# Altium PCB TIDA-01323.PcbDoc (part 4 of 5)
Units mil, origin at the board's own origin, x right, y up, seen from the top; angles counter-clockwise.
Board outline 2467 x 6135 mil, 6 copper layers (Layer 1 - Top Layer, Layer 2 - GND, Layer 3 - Sensitive, Layer 4 - GND, Layer 5 - PWR, Layer 6 - Bottom Layer), stack 62.468 mil thick; 310 components, 202 nets, 881 pads, 527 vias.
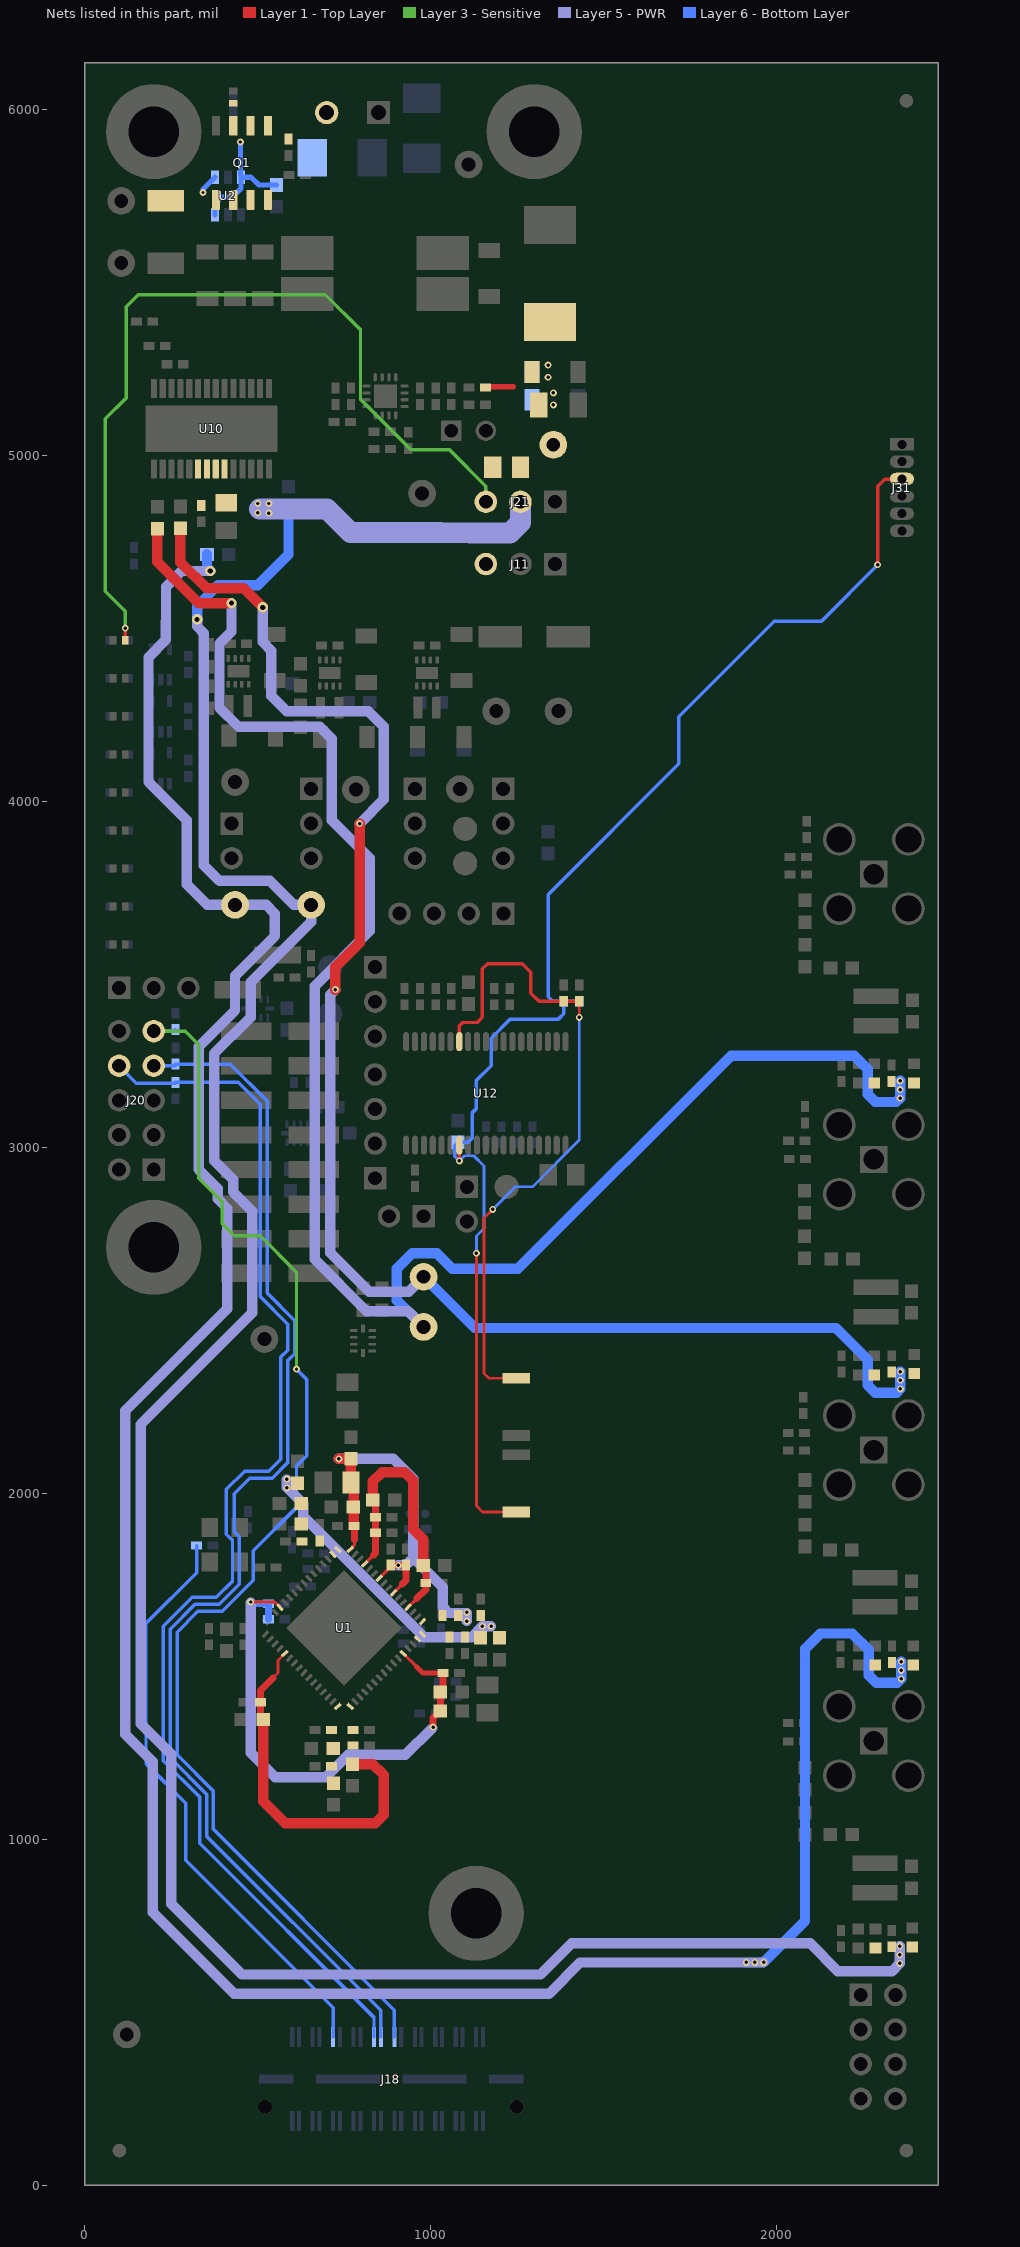
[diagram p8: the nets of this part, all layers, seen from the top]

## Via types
v1: diameter 20, hole 10, Layer 1 - Top Layer to Layer 6 - Bottom Layer, tented both sides, 397 vias
v2: diameter 19.68, hole 7.87, Layer 1 - Top Layer to Layer 6 - Bottom Layer, tented both sides, 64 vias
v3: diameter 12, hole 6, Layer 1 - Top Layer to Layer 6 - Bottom Layer, tented both sides, 58 vias
v4: diameter 30, hole 15, Layer 1 - Top Layer to Layer 6 - Bottom Layer, tented both sides, 8 vias

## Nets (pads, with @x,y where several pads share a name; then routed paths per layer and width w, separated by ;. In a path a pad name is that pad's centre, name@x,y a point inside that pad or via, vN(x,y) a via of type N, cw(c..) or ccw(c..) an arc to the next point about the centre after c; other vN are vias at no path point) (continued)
SPI_MOSI_0: J18.18 J20.8 R56.2 | length 3681.3
  Layer 6 - Bottom Layer w10: J20.8@99.38,3235.87 149.38,3185.87 R56.2@262,3185.87 ; R56.2@262,3187.62 443.38,3187.62 507,3124 507,2569 587,2489 587,2414 567,2394 567,2099 532,2064 462,2064 409.38,2011.38 409.38,1881.62 427,1864 427,1745.57 380.43,1699 310.43,1699 227,1615.57 227,1227.28 332,1122.28 332,989 836.01,484.99 J18.18@836.01,428.52
SPI_NCS_0: J18.22 J20.9 R58.2 | length 3708.8
  Layer 3 - Sensitive w10: J20.9@199.38,3335.87 290.13,3335.87 329.38,3296.62 329.38,2910.75 397,2843.13 397,2779 432,2744 507,2744 612,2639 v1(612,2359)
  Layer 6 - Bottom Layer w10: J20.9@199.38,3335.87 257.49,3335.87 R58.2@262,3340.38 ; v1(612,2359) 642,2329 642,2109 612,2079 612,1959 487,1834 487,1749 397,1659 327,1659 267,1599 267,1243.85 372,1138.85 372,1029 895.06,505.94 J18.22@895.06,428.52
SPI_SCLK_0: J18.20 J20.7 R57.2 | length 3603.1
  Layer 6 - Bottom Layer w10: J20.7@199.38,3235.87 R57.2@262,3235.87 ; R57.2@262,3240.38 420.62,3240.38 527,3134 527,2579 607,2499 607,2404 587,2384 587,2089 542,2044 477,2044 432,1999 432,1889 447,1874 447,1737.28 388.72,1679 318.72,1679 247,1607.28 247,1235.57 352,1130.57 352,1009 855.69,505.31 J18.20@855.69,428.52
SYS_CLK_25MHZ: J18.10 R45.2 | length 1705.2
  Layer 6 - Bottom Layer w10: R45.2@323.38,1849 323.38,1770.38 177,1624 177,1219 292,1104 292,939 717.9,513.1 J18.10@717.9,428.52
TDIO1: C107.1 J31.3 R92.1 R103.1 S1.1 U12.7 | length 4074.7
  Layer 1 - Top Layer w8: v1(1132,2694) 1132,1964.09 1150,1946.09 S1.1@1247.38,1946.09
  Layer 1 - Top Layer w10: v1(1082.61,2960.87) U12.7@1082.61,3006.26 ; v1@2292.38,4683.49 2292.38,4910.87 2312.38,4930.87 J31.3@2367.38,4930.87
  Layer 6 - Bottom Layer w8: v1(1082.61,2960.87) 1097.61,2975.87 1124.38,2975.87 1154.38,2945.87 1154.38,2765.87 1132,2743.49 v1(1132,2694)
  Layer 6 - Bottom Layer w10: v1(1082.61,2960.87) 1069.38,2974.1 1069.38,3004.37 R103.1@1079.38,3014.37 1107.88,3014.37 1119.38,3025.87 1119.38,3099.3 1130.95,3110.87 1130.95,3192.44 1174.38,3235.87 1174.38,3315.87 1229.38,3370.87 1369.38,3370.87 1384.38,3385.87 R92.1@1384.38,3422.25 ; C107.1@1429.38,3422.25 R92.1@1384.38,3422.25 ; v1(2292,4684) 2292,4683.49 2129.51,4521 1993,4521 1717,4245 1717,4108.49 1339.38,3730.87 1339.38,3435.87 1353,3422.25 R92.1@1384.38,3422.25
USER_BUTTON: C111.1 R110.1 S2.1 U12.32 | length 1946.5
  Layer 1 - Top Layer w8: v1(1179.38,2820.87) 1154.38,2795.87 1154.38,2346.62 1168.32,2332.68 S2.1@1247.38,2332.68 ; v1(1429.38,3375.87) C111.1@1429.38,3422.25
  Layer 1 - Top Layer w10: U12.32@1082.61,3305.48 1082.61,3350.87 1092.61,3360.87 1134.38,3360.87 1149.38,3375.87 1149.38,3515.87 1164.38,3530.87 1264.38,3530.87 1289.38,3505.87 1289.38,3445.87 1313,3422.25 R110.1@1384.38,3422.25 C111.1@1429.38,3422.25
  Layer 6 - Bottom Layer w8: v1(1179.38,2820.87) 1244.38,2885.87 1294.38,2885.87 1429.38,3020.87 v1(1429.38,3375.87)
V_CAM: C96.1 C97.1 J21.2 U10.20 U10.21 U10.22 U10.23 | length 855
  Layer 5 - PWR w60: 505,4845 700,4845 768,4777 1028,4777 1114.38,4775.87 1229.38,4775.87 1259.38,4805.87 J21.2@1259.38,4865.87
  other v1: 532,4833 500,4834 500,4861 532,4861
V_CAM1: C3.1 C4.1 L1.1 R64.1 TP21.1 | length 7111.6
  Layer 5 - PWR w30: v4(324.73,4526) 324.73,4505.51 344.38,4485.87 344.38,3815.87 389.38,3770.87 534.38,3770.87 604.38,3700.87 TP21.1@654.38,3700.87 654.38,3651.87 479.38,3476.87 479.38,3376.38 374.38,3271.38 374.38,2960.87 429.38,2905.87 429.38,2870.87 484.38,2815.87 484.38,2521.38 162,2199 162,1334 250.28,1245.72 250.28,814 455.28,609 1317,609 1407,699 2097,699 2177,619 2333.49,619 v1(2355.62,641.13) v1(2355.62,691.13)
  Layer 6 - Bottom Layer w30: v4(324.73,4526) 324.73,4564.73 385,4625 500,4625 589,4714 R64.1@589,4846.5
  other v1: 2355.62,666.13
V_CAM2: C7.1 C8.1 L2.1 R66.1 TP22.1 | length 7949.6
  Layer 5 - PWR w30: v4(363,4666) 281,4666 234.95,4619.95 234.95,4582 234.38,4466.74 184.38,4416.74 184.38,4055.87 294.38,3945.87 294.38,3760.87 354.38,3700.87 TP22.1@434.38,3700.87 524.38,3700.87 549.38,3675.87 549.38,3610.87 434.38,3495.87 434.38,3396.38 329.38,3291.38 329.38,2935.87 384.38,2880.87 384.38,2850.87 412,2823.25 412,2534 117,2239 117,1304 197,1224 197,789 432,554 1342,554 1432,644 v1(1912,644) v1(1937,644) v1(1962,644)
  Layer 6 - Bottom Layer w10: v4(363,4666) v4@363,4674.73
  Layer 6 - Bottom Layer w30: R66.1@353.5,4714 353.5,4675.5 v4(363,4666) ; v1(1912,644) v1(1962,644) 2082,764 2082,1551 2125.72,1594.72 2218.72,1594.72 2265.94,1547.5 2265.94,1474.42 2287.87,1452.49 2349.13,1452.49 v1(2360,1463.36) v1(2360,1513.36)
  other v1: 2360,1488.36
V_CAM3: C17.1 C18.1 L9.1 R78.1 TP23.1 | length 4550.8
  Layer 1 - Top Layer w30: R78.1@276.29,4789.5 276.29,4691.71 352,4616 459.26,4616 v4(514.38,4560.87) ; v1(724.38,3455.87) 724.38,3520.87 794.38,3590.87 v1(794.38,3935.87)
  Layer 5 - PWR w30: v4(514.38,4560.87) 514.38,4460.87 539.38,4435.87 539.38,4305.87 584.38,4260.87 819.38,4260.87 864.38,4215.87 864.38,4005.87 v1(794.38,3935.87) ; v1(724.38,3455.87) 709.38,3440.87 709.38,2695.87 822.73,2582.52 936.03,2582.52 TP23.1@979.38,2625.87
  Layer 6 - Bottom Layer w30: TP23.1@979.38,2625.87 1127.25,2478 2171.33,2478 2263.32,2386.01 2263.32,2312.93 2285.25,2291 2346.51,2291 v1(2357.38,2301.87) v1(2357.38,2326.87) v1(2357.38,2351.87)
V_CAM4: C21.1 C22.1 L10.1 R80.1 TP24.1 | length 5150.6
  Layer 1 - Top Layer w30: R80.1@209.81,4787.5 209.81,4692.19 329,4573 v4(424,4573)
  Layer 5 - PWR w30: v4(424,4573) 424,4490.49 389.38,4455.87 389.38,4270.87 444.38,4215.87 679.38,4215.87 714.38,4180.87 714.38,3945.87 824.38,3835.87 824.38,3625.87 664.38,3465.87 664.38,2675.87 814.38,2525.87 934.38,2525.87 TP24.1@979.38,2480.87
  Layer 6 - Bottom Layer w30: TP24.1@979.38,2480.87 902,2558.25 902,2649 947,2694 1017,2694 1062,2649 1252,2649 1868,3265 2224.08,3265 2262.94,3226.14 2262.94,3153.06 2284.87,3131.13 2346.13,3131.13 v1(2357,3142) v1(2357,3192)
  other v1: 2357,3167
V_MAIN: D5.2 J11.3 J21.3 R19.2 | length 2459.8
  Layer 1 - Top Layer w10: D5.2@117.1,4465.87 v1(117.1,4500.87)
  Layer 3 - Sensitive w10: v1(117.1,4500.87) 117.1,4549.9 59.38,4607.62 59.38,5105.87 119.38,5165.87 119.38,5430 154.38,5465 695.25,5465 797,5363.25 797,5162 943.13,5015.87 1054.38,5015.87 1159.38,4910.87 J21.3@1159.38,4865.87
VBAT: C29.1 C30.1 D1.1 D2.1 J5.2 Q1.1 Q1.2 Q1.3 U2.3 U2.6 | length 364.4
  Layer 6 - Bottom Layer w15: U2.3@376.52,5695.87 376.52,5727.52 395,5746 426,5746 451.33,5771.33 U2.6@451.33,5804.13 480.87,5804.13 503.5,5781.5 C30.1@553.67,5781.5 ; U2.6@450,5810.7 v1(450,5906)
VBAT_PROTECT: Q1.5 Q1.6 Q1.7 Q1.8 R17.1 U2.4 | length 58.5
  Layer 6 - Bottom Layer w15: v1(341.78,5760) 341.78,5769.39 U2.4@376.52,5804.13
VDD18_P0: C67.1 C68.1 C69.1 C71.1 C72.1 C75.1 C76.1 C78.1 C79.1 L23.2 U1.1 U1.2 U1.47 U1.48 | length 824.9
  Layer 5 - PWR w30: v1@584.38,2039 584.38,2017.87 632,1970.25 632,1934 981.51,1584.49 1118,1584.49 v1(1149.38,1615.87) v1(1174.38,1615.87)
  other v1: 584.38,2015.87 584.38,2040.87
VDD18A: C57.1 C58.1 C59.1 L21.2 U1.32
VDDCSI_1V1: C88.1 C89.1 C90.1 C91.1 L25.2 U1.21 U1.33 | length 1063.3
  Layer 1 - Top Layer w8: 543.88,1466.37 558.22,1480.71 558.22,1517.17 U1.21@578.16,1537.11
  Layer 1 - Top Layer w20: C89.1@515.88,1345.87 508,1353.74 C90.1@508,1395.87 508,1430.49 543.88,1466.37
  Layer 1 - Top Layer w30: C89.1@515.88,1345.87 515.88,1109.37 579.38,1045.87 839.38,1045.87 864.38,1070.87 864.38,1185.87 832.88,1217.37 L25.2@774.38,1217.37
VDDFPD18: C60.1 C61.1 C62.1 C63.1 C64.1 C65.1 C66.1 L22.2 U1.49 U1.55 U1.58 U1.64 | length 1282.6
  Layer 1 - Top Layer w9: U1.64@767.45,1837.78 779.38,1849.71 779.38,1865.87 ; U1.58@850.99,1754.24 C64.1@884.38,1787.64 ; U1.55@892.75,1712.48 917.76,1737.49
  Layer 1 - Top Layer w20: C65.1@778,1905.87 779.38,1904.49 779.38,1865.87 ; C64.1@884.38,1792.25 884.76,1791.87 v1(906.38,1791.87) C61.1@928,1791.87 ; 917.76,1737.49 928.38,1748.1 C61.1@928.38,1792.25
  Layer 1 - Top Layer w30: v1(734.38,2099.37) L22.2@769.38,2099.37 ; L22.2@769.38,2094.37 769.38,2025.87 778,2017.25 C65.1@778,1905.87
  Layer 5 - PWR w30: v1(734.38,2099.37) 891.63,2099.37 949.38,2041.62 949.38,1813.25 ; v1(906.38,1791.87) 928,1791.87 949.38,1813.25 ; v1(1104.38,1630.87) 1104.38,1654 1052,1654 1034.38,1671.62 1034.38,1728.25 949.38,1813.25
  other v1: 1104.38,1655.87
VDDFPD_1V1: C92.1 C93.1 C94.1 C95.1 L26.2 U1.52 U1.61 | length 794
  Layer 1 - Top Layer w9: U1.61@809.22,1796.01 834.23,1821.02 ; U1.52@934.52,1670.71 959.53,1695.72
  Layer 1 - Top Layer w20: L26.2@832.88,1980.87 840.76,1973 C92.1@840.76,1930.87 C95.1@840.76,1885.87 840.76,1827.55 834.23,1821.02 ; 959.53,1695.72 985.76,1721.94 C94.1@985.76,1740.87 985.76,1783 C93.1@977.88,1790.87
  Layer 1 - Top Layer w30: L26.2@832.88,1980.87 832.88,2034.37 859.38,2060.87 924.38,2060.87 949.38,2035.87 949.38,1895.87 977.88,1867.37 C93.1@977.88,1790.87
VDDL_1V1: C81.1 C82.1 C83.1 C84.1 L24.2 U1.13 U1.44 | length 1539.1
  Layer 1 - Top Layer w8: v1(479.38,1685.87) 549.1,1685.87 U1.13@564.25,1670.72
  Layer 1 - Top Layer w9: U1.44@920.59,1537.1 959.38,1498.31
  Layer 1 - Top Layer w15: 959.38,1498.31 976.82,1480.87 C84.1@1035.76,1480.87
  Layer 1 - Top Layer w20: v1(1007,1324) 1007,1349.99 L24.2@1027.88,1370.87 C82.1@1027.88,1425.87 ; C82.1@1027.88,1430.87 1035.76,1438.74 C84.1@1035.76,1480.87
  Layer 5 - PWR w30: v1@479.38,1684 479.38,1250.5 550.88,1179 697,1179 762,1244 927,1244 v1@1004.5,1321.5
  Layer 6 - Bottom Layer w20: v1(479.38,1685.87) 484.38,1680.87 C83.1@530.76,1680.87 C81.1@530.76,1635.87
VOUT_SEPIC: C33.1 C34.1 C35.1 D4.1 R19.1 R20.2 R24.1 TP6.1 | length 79.4
  Layer 1 - Top Layer w15: R24.1@1160.01,5198.37 1239.38,5198.37
  other v1: 1354.38,5145.87 1354.38,5180.87 1339.38,5225.87 1339.38,5260.87
pads on no net: FID1.1 FID2.1 FID3.1 FID4.1 FID5.1 FID6.1 H1. H2. H3. H4. J18.MH1 J18.MH2 J20.4 J20.6 J31.1 J31.6 R52.2 U1.7 U1.8 U10.2 U10.19 U10.24 U10.29@366,5077 U12.23 U14.1 U14.2 U15.1 U15.2

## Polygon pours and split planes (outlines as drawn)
GND on Layer 2 - GND "Layer 2 - GND - GND" (solid, remove dead copper, pour order 0): 20,6115 20,20 2447,20 2447,6115
GND on Layer 4 - GND "Layer 4 - GND - GND" (solid, remove dead copper, pour order 2): 20,6115 20,20 2447,20 2447,6115

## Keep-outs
Keep-Out Layer:
  text ".Layer_Name" at -2051,-674.49 h60

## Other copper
Layer 1 - Top Layer:
  region net NetR64_2: 498,4988.39 541,4988.39 541,4895 498,4895
  region net NetR66_2: 447,4932 447,4988 490.47,4988 490.47,4895 447,4895
  region net GND: 311,4743 311,4826 371.6,4826 383.6,4814 441,4814 453,4802 489,4802 489,4798 489,4743
  region net VDD18_P0: 698.38,1878.87 660.38,1878.87 646.38,1892.87 646.38,2038.87 634.38,2050.87 579.38,2050.87 574.38,2045.87 574.38,2010.87 579.38,2005.87 596.38,2005.87 605.38,1996.87 605.38,1979.87 605.38,1888.87 611.38,1882.87 611.38,1848.87 614.38,1845.87 688.38,1845.87 722.38,1811.87 743.38,1832.87 744.38,1832.87
  region net GND: 597.38,1848.87 597.38,1872.87 583.38,1886.87 583.38,1989.87 542.38,1989.87 519.38,1966.87 519.38,1893.87 564.38,1848.87
  region net GND: 474.38,1580.87 474.38,1545.87 452.38,1523.87 386.38,1523.87 374.38,1535.87 324.38,1535.87 319.38,1540.87 319.38,1575.87 324.38,1580.87 374.38,1580.87 389.38,1565.87 429.38,1565.87 444.38,1580.87
  region net GND: 684.38,1327.87 684.38,1198.87 649.38,1198.87 634.38,1213.87 634.38,1312.87 649.38,1327.87
  region net VDD18A: 696.38,1355.87 696.38,1141.87 738.38,1141.87 742.38,1145.87 742.38,1389.87 736.38,1395.87
  region net VDD18_P0: 966.38,1567.87 1119.38,1567.87 1125.38,1561.87 1224.38,1561.87 1224.38,1630.87 1189.38,1665.87 1131.38,1665.87 1131.38,1612.87 1122.38,1603.87 1102.38,1603.87 970.38,1603.87 950.38,1583.87
  region net GND: 479.38,1410.87 419.38,1410.87 409.38,1400.87 409.38,1330.87 419.38,1320.87 479.38,1320.87
  region net GND: 794.38,2285.87 794.38,2345.87 724.38,2345.87 704.38,2325.87 704.38,2285.87
  region net GND: 747.38,1892.87 668.38,1892.87 664.38,1896.87 664.38,2062.87 715.38,2062.87 715.38,1997.87 739.38,1973.87 739.38,1925.87 747.38,1917.87
  region net GND: 839.38,1327.87 839.38,1258.87 805.38,1258.87 805.38,1327.87
  region net GND: 1014.38,1685.87 1022.38,1677.87 1109.38,1677.87 1114.38,1682.87 1114.38,1720.87 1109.38,1725.87 1079.38,1725.87 1064.38,1740.87 1064.38,1825.87 1059.38,1830.87 1019.38,1830.87 1014.38,1825.87
  region net GND: 1042.38,1553.87 1111.38,1553.87 1125.38,1539.87 1218.38,1539.87 1218.38,1440.87 1197.38,1419.87 1124.38,1419.87 1111.38,1406.87 1071.38,1406.87 1066.38,1411.87 1066.38,1496.87 1042.38,1520.87
  region net VDDFPD18: 970.38,1617.87 1109.38,1617.87 1114.38,1622.87 1114.38,1660.87 1109.38,1665.87 1005.38,1665.87 964.38,1624.87 964.38,1623.87
  region net VDDCSI_1V1: 762.38,1395.87 794.38,1363.87 794.38,1195.87 754.38,1195.87 754.38,1387.87
  region net GND: 409.38,4361.87 413.38,4357.87 482.38,4357.87 488.38,4363.87 510.38,4363.87 516.38,4357.87 516.38,4134.87 581.38,4134.87 581.38,4358.87 595.38,4372.87 642.38,4372.87 662.38,4352.87 742.38,4352.87 747.38,4357.87 773.38,4357.87 778.38,4352.87 778.38,4230.87 767.38,4219.87 767.38,4151.87 839.38,4151.87 850.38,4162.88 863.38,4175.87 863.38,4361.87 874.38,4372.87 937.38,4372.87 957.38,4352.87 1024.38,4352.87 1030.38,4358.87 1050.38,4358.87 1056.38,4352.87 1056.38,4230.87 1043.38,4217.87 1043.38,4139.87 1112.38,4139.87 1121.38,4148.87 1121.38,4230.87 1121.38,4399.87 1102.38,4418.87 1013.38,4418.87 1013.38,4393.87 1008.38,4388.87 973.38,4388.87 965.38,4396.87 965.38,4416.87 961.38,4420.87 736.38,4420.87 732.38,4416.87 732.38,4392.87 728.38,4388.87 690.38,4388.87 684.38,4394.87 684.38,4416.87 677.38,4423.87 470.38,4423.87 468.38,4421.87 468.38,4397.87 464.38,4393.87 427.38,4393.87 420.38,4400.87 420.38,4421.87 415.38,4426.87 409.38,4426.87
  region net V_CAM3: 2265.38,2368.87 2414.38,2368.87 2414.38,2305.87 2397.51,2289 2287.25,2289 2265.38,2310.87
  region net NetC29_2: 569.38,5885.87 569.38,5795.87 609.38,5795.87 609.38,5885.87
  region net GND: 2172.38,2368.87 2254.38,2368.87 2254.38,2325.87 2246.51,2318 2183.25,2318 2172.38,2328.87
  region net GND: 2170.62,706 2255.62,706 2255.62,673.13 2235.62,653.13 2185.62,653.13 2170.62,668.13
  region net NetC15_1: 2221.72,2544 2413,2544 2413,2448 2318,2448 2300,2430 2300,2381 2174,2381 2174,2430 2221.72,2490
  region net NetL3_1: 2101.62,1164.13 2101.62,1128.63 2101.62,1087.63 2101.62,1055.63 2058.84,1055.63 2058.84,1070.63 2058.84,1090.63 2058.84,1117.27 2058.84,1141.63 2058.84,1164.13
  region net NetC1_1: 2218.62,878.13 2410.62,878.13 2410.62,788.13 2315.62,788.13 2302.62,775.13 2302.62,721 2168.62,721 2168.62,768.13 2218.62,818.13
  region net NetL4_1: 2410.62,900.13 2410.62,1053.13 2390.62,1053.13 2325.62,1053.13 2259.62,1053.13 2209.62,1053.13 2194.62,1038.13 2194.62,985.13 2218.62,953.13 2218.62,900.13
  region net GND: 1459.38,5295.87 1409.38,5295.87 1400.38,5286.87 1400.38,5089.87 1409.38,5080.87 1459.38,5080.87
  region net LOCAL_1V1: 440.38,4348.87 440.38,4235.87 474.38,4201.87 474.38,3900.87 389.38,3900.87 374.38,3915.87 374.38,4205.87 334.38,4245.87 334.38,4290.87 379.38,4290.87 399.38,4310.87 417.38,4310.87 429.38,4322.87 429.38,4348.87
  region net VBAT_PROTECT: 544.38,5770.87 179.38,5770.87 179.38,5680.87 199.38,5660.87 524.38,5660.87 544.38,5680.87
  region net VBAT: 709.38,6030.87 739.38,6000.87 739.38,5925.87 709.38,5895.87 414.38,5895.87 414.38,6030.87
  region net GND: 874.38,5241.36 884.38,5251.36 1026.38,5251.36 1026.38,5178.36 955.38,5178.36 933.38,5156.36 908.38,5156.36 903.38,5151.36 903.38,5137.36 872.38,5137.36 864.38,5129.36 864.38,5099.36 852.38,5087.36 852.38,4991.36 738.89,4991.36 674.38,5055.87 674.38,5164.36 736.38,5164.36 736.38,5078.36 748.38,5066.36 803.38,5066.36 835.38,5098.36 835.38,5205.36 869.38,5205.36 874.38,5210.36
  region net GND: 1334.38,4565.87 1334.38,4385.87 1464.38,4385.87 1464.38,4565.87
  region net NetL20_1: 448.38,4348.87 448.38,4250.87 458.38,4240.87 484.38,4240.87 484.38,4307.87 477.38,4314.87 466.38,4314.87 459.38,4321.87 459.38,4348.87
  region net NetL19_1: 712.38,4343.87 712.38,4245.87 722.38,4235.87 748.38,4235.87 748.38,4302.87 741.38,4309.87 730.38,4309.87 723.38,4316.87 723.38,4343.87
  region net LOCAL_1V8: 693.38,4343.87 693.38,4317.87 685.38,4309.87 667.38,4309.87 659.38,4301.87 659.38,4247.87 647.38,4235.87 603.38,4235.87 603.38,3990.87 799.38,3990.87 823.38,4014.87 823.38,4056.87 799.38,4080.87 734.38,4080.87 704.38,4110.87 704.38,4343.87
  region net NetC36_1: 54.38,5605.87 84.38,5635.87 769.38,5635.87 834.38,5570.87 834.38,5370.87 784.38,5320.87 784.38,5197.87 796.38,5185.87 826.38,5185.87 826.38,5175.87 709.38,5175.87 699.38,5185.87 699.38,5370.87 739.38,5410.87 739.38,5518.87 723.38,5534.87 343.38,5534.87 319.38,5510.87 84.38,5510.87 54.38,5540.87
  region net NetC32_2: 805.38,5194.87 800.38,5199.87 800.38,5306.87 854.38,5360.87 854.38,5430.87 939.38,5515.87 1179.38,5515.87 1204.38,5490.87 1204.38,5375.87 1114.38,5285.87 895.38,5285.87 864.38,5254.87 864.38,5216.87 861.38,5213.87 832.38,5213.87 826.38,5207.87 826.38,5197.87 823.38,5194.87
  region net NetC32_1: 958.38,5534.87 1363.38,5534.87 1424.38,5595.87 1424.38,5725.87 1043.38,5725.87 958.38,5640.87
  region net VOUT_SEPIC: 1424.38,5445.87 1269.38,5445.87 1254.38,5430.87 1254.38,5220.87 1239.38,5205.87 1239.38,5190.87 1254.38,5175.87 1254.38,5030.87 1234.38,5010.87 1234.38,4933.87 1242.38,4925.87 1384.38,4925.87 1394.38,4935.87 1399.63,4941.12 1399.63,5065.62 1384.38,5080.87 1384.38,5294.87 1394.38,5304.87 1424.38,5334.87
  region net GND: 716.38,5519.87 721.38,5514.87 721.38,5417.87 694.38,5390.87 564.38,5390.87 526.88,5428.37 319.38,5428.37 319.38,5485.87 353.38,5519.87
  region net V_CAM: 317.62,4837 317.62,4988.87 414,4988.87 414,4916 437.95,4892.05 454,4876 551,4876 551,4819.99 551,4818.68 453.32,4818.68 435,4837
  region net EXT_VIN: 1324.38,4900.87 1394.38,4900.87 1394.38,4650.87 1324.38,4650.87
  region net V_MAIN: 1124.38,5005.87 1204.38,5005.87 1204.38,4650.87 1124.38,4650.87
  region net NetL18_1: 993.38,4343.87 993.38,4245.87 1003.38,4235.87 1029.38,4235.87 1029.38,4302.87 1022.38,4309.87 1011.38,4309.87 1004.38,4316.87 1004.38,4343.87
  region net NetC43_1: 1294.38,4720.87 1294.38,4295.87 1214.38,4215.87 1144.38,4215.87 1144.38,4405.87 1112.38,4437.87 1016.38,4437.87 1004.38,4425.87 1004.38,4397.87 993.38,4397.87 993.38,4471.87 979.38,4485.87 897.88,4485.87 848.38,4436.37 735.88,4436.37 723.38,4423.87 723.38,4397.87 711.88,4397.87 711.88,4479.37 705.38,4485.87 674.38,4485.87 654.38,4485.87 610.38,4441.87 472.38,4441.87 459.38,4428.87 459.38,4402.87 448.38,4402.87 448.38,4494.87 474.38,4520.87 514.38,4520.87 674.38,4520.87 699.38,4545.87 1009.38,4545.87 1144.38,4545.87 1224.38,4625.87 1224.38,4720.87
  region net LOCAL_3V3: 974.38,4343.87 974.38,4317.87 966.38,4309.87 948.38,4309.87 894.25,4309.87 884.38,4300 884.38,4002.87 1049.38,4002.87 1057.38,3994.87 1103.38,3994.87 1111.38,4002.87 1124.38,4015.87 1124.38,4055.87 1099.38,4080.87 1015.38,4080.87 985.38,4110.87 985.38,4343.87
  region net V_CAM1: 2268.62,706 2412.62,706 2412.62,645.13 2398.62,631.13 2287.62,631.13 2268.62,650.13
  region net GND: 20,6115 20,40 40,40 40,6095 2426,6095 2426,40 20,40 20,20 2447,20 2447,6115
  region net GND: 2320,5001 2320,4963 2403,4963 2403,5001
  region net NetL3_2: 2175.62,980.13 2175.62,1034.13 2054.62,1034.13 2054.62,980.13
  region net NetL5_1: 2062.61,1888.87 2062.61,1923.87 2062.61,1961.87 2062.61,1995.87 2105.95,1995.87 2105.95,1980.87 2105.95,1957.87 2105.95,1926.3 2105.95,1902.87 2105.95,1888.87
  region net NetL5_2: 2174.62,1816.13 2174.62,1869.13 2051.49,1869.13 2051.49,1829.13 2051.49,1816.13
  region net NetL12_1: 2412.5,2563 2412.5,2715 2392.5,2715 2327.5,2715 2261.5,2715 2211.5,2715 2197.5,2701 2197.5,2645.24 2221.5,2616.98 2221.5,2563
  region net NetL11_1: 2100.67,2831 2100.67,2801.77 2100.67,2760 2100.67,2724 2057.33,2724 2057.33,2736 2057.33,2763 2057.33,2793.57 2057.33,2819 2057.33,2831
  region net NetL13_1: 2060.74,3561.02 2060.74,3597.94 2060.74,3641 2060.74,3669.02 2103.8,3669.02 2103.8,3664.02 2103.8,3654.02 2103.8,3631.94 2103.8,3597.94 2103.8,3561.02
  region net NetL13_2: 2185.07,3494 2185.07,3544 2061.94,3544 2061.94,3524 2061.94,3503 2061.94,3494
  region net NetL11_2: 2179.5,2649 2179.5,2703 2058.5,2703 2058.5,2649
  region net GND: 2122,1234 2122,1135 2437,1135 2437,1435 2122,1435 2122,1334 2347,1334 2347,1234
  region net NetL6_1: 2409.62,1722.13 2409.62,1875.13 2389.62,1875.13 2324.62,1875.13 2258.62,1875.13 2208.62,1875.13 2193.62,1860.13 2193.62,1807.13 2217.62,1775.13 2217.62,1722.13
  region net NetC5_1: 2218.62,1702.13 2410.62,1702.13 2410.62,1612.13 2315.62,1612.13 2302.62,1599.13 2302.62,1542.13 2168.62,1542.13 2168.62,1592.13 2218.62,1642.13
  region net GND: 2169,1528 2254,1528 2254,1486 2243,1475 2181,1475 2169,1487
  region net V_CAM2: 2268,1528 2412,1528 2412,1463 2398,1449 2287,1449 2268,1468
  region net GND: 2320,721 2431,721 2431,769 2335,769 2320,754
  region net GND: 2319,1542 2430,1542 2430,1588 2334,1588 2319,1573
  region net GND: 2318.38,2380.87 2429.38,2380.87 2429.38,2426.87 2333.38,2426.87 2318.38,2411.87
  region net GND: 2172,3209 2254,3209 2254,3166 2245.87,3157.87 2183.13,3157.87 2172,3169
  region net V_CAM4: 2265,3209 2414,3209 2414,3146 2397.13,3129.13 2286.87,3129.13 2265,3151
  region net GND: 2318,3221 2429,3221 2429,3267 2333,3267 2318,3252
  region net NetC19_1: 2221.34,3384.13 2412.62,3384.13 2412.62,3288.13 2317.62,3288.13 2299.62,3270.13 2299.62,3221.13 2173.62,3221.13 2173.62,3270.13 2221.34,3330.13
  region net NetL14_1: 2412.5,3404 2412.5,3556 2392.5,3556 2327.5,3556 2261.5,3556 2211.5,3556 2197.5,3542 2197.5,3486.24 2221.5,3457.98 2221.5,3404
  region net GND: 2121.3,2074 2121.3,1975 2436.3,1975 2436.3,2275 2121.3,2275 2121.3,2174 2346.3,2174 2346.3,2074
  region net GND: 2121.3,2914 2121.3,2815 2436.3,2815 2436.3,3115 2121.3,3115 2121.3,3014 2346.3,3014 2346.3,2914
  region net GND: 2123.3,3741 2123.3,3640 2438.3,3640 2438.3,3940 2123.3,3940 2123.3,3841 2348.3,3841 2348.3,3741
  region net GND: 1207,2184 1207,2094 1287,2094 1287,2184
  region net GND: 174.62,5009.06 174.62,5144.93 216,5144.93 216,5328 261,5328 261,5145 523,5145 523,5220 557,5220 557,5144.93 557,5009.07 234,5009.06
  region net NetR80_2: 190,4932 190,4988 233.47,4988 233.47,4895 190,4895
  region net NetR78_2: 242,4988.39 285,4988.39 285,4895 242,4895
  text ".Layer_Name" at -2051,-674.49 h60
Layer 2 - GND:
  pour cut-out: 774.39,1830.88 969.39,1635.88 1004.39,1635.88 1004.39,1665.88 804.39,1865.88 774.39,1865.88
  region net GND: 1469.38,4150.87 1459.38,4150.87 1459.38,3820.87 1469.38,3820.87
  pour cut-out: 2311.5,4963 2311.5,4743 2411.5,4743 2411.5,4963
  region net GND: 992.87,2895.39 992.87,2886.36 979.38,2872.87 971.38,2872.87 971.38,2895.39
  region net GND: 1276.38,2945.87 1290.38,2959.87 1294.38,2959.87 1294.38,2925.87 1288.38,2925.87 1276.38,2937.87
  pour cut-out: 789.38,3560.87 789.38,3360.87 889.38,3360.87 889.38,3560.87
  pour cut-out: 889.38,3160.87 889.38,2860.87 789.38,2860.87 789.38,3160.87
  pour cut-out: 1029.38,2750.87 1029.38,2850.87 829.38,2850.87 829.38,2750.87
  pour cut-out: 1054.38,2735.87 1154.38,2735.87 1154.38,2921.37 1134.88,2940.87 1054.38,2940.87
  pour cut-out: 1014.38,5120.87 1014.38,5025.87 1204.38,5025.87 1204.38,5120.87
  pour cut-out: 1109.38,4815.87 1409.38,4815.87 1409.38,4915.87 1109.38,4915.87
  pour cut-out: 1109.38,4735.87 1109.38,4635.87 1409.38,4635.87 1409.38,4735.87
  pour cut-out: 959.38,3725.87 959.38,3625.87 1259.38,3625.87 1259.38,3725.87
  pour cut-out: 1159.38,4085.87 1159.38,3785.87 1259.38,3785.87 1259.38,4085.87
  pour cut-out: 904.38,4085.87 904.38,3785.87 974.38,3785.87 1004.38,3815.87 1004.38,4085.87
  pour cut-out: 604.38,4085.87 604.38,3785.87 704.38,3785.87 704.38,4085.87
  pour cut-out: 374.38,3985.87 374.38,3785.87 474.38,3785.87 474.38,3985.87
  pour cut-out: 49.38,3510.87 49.38,3410.87 349.38,3410.87 349.38,3510.87
  pour cut-out: 149.38,3385.87 149.38,3285.87 49.38,3285.87 49.38,2985.87 149.38,2985.87 149.38,2885.87 249.38,2885.87 249.38,3385.87
  region net GND: 1459.38,700.87 1459.38,300.87 1479.38,300.87 1479.38,700.87
  pour cut-out: 2195,599.87 2195,199.87 2390,199.87 2390,599.87
  pour cut-out: 773.71,1390.2 913.71,1530.2 948.71,1530.2 948.71,1500.2 808.71,1360.2 773.71,1360.2
  pour cut-out: 584.38,1530.87 724.38,1390.87 724.38,1355.87 694.38,1355.87 554.38,1495.87 554.38,1530.87
  text ".Layer_Name" at -2051,-674.49 h60
Layer 3 - Sensitive:
  text ".Layer_Name" at -2051,-674.49 h60
Layer 4 - GND:
  pour cut-out: 774.39,1830.88 969.39,1635.88 1004.39,1635.88 1004.39,1665.88 804.39,1865.88 774.39,1865.88
  region net GND: 1459.38,700.87 1459.38,300.87 1479.38,300.87 1479.38,700.87
  region net GND: 1276.38,2945.87 1290.38,2959.87 1294.38,2959.87 1294.38,2925.87 1288.38,2925.87 1276.38,2937.87
  region net GND: 992.87,2895.39 992.87,2886.36 979.38,2872.87 971.38,2872.87 971.38,2895.39
  region net GND: 1469.38,4150.87 1459.38,4150.87 1459.38,3820.87 1469.38,3820.87
  pour cut-out: 584.38,1530.87 724.38,1390.87 724.38,1355.87 694.38,1355.87 554.38,1495.87 554.38,1530.87
  pour cut-out: 773.71,1390.2 913.71,1530.2 948.71,1530.2 948.71,1500.2 808.71,1360.2 773.71,1360.2
  pour cut-out: 2195,599.87 2195,199.87 2390,199.87 2390,599.87
  pour cut-out: 149.38,3385.87 149.38,3285.87 49.38,3285.87 49.38,2985.87 149.38,2985.87 149.38,2885.87 249.38,2885.87 249.38,3385.87
  pour cut-out: 49.38,3510.87 49.38,3410.87 349.38,3410.87 349.38,3510.87
  pour cut-out: 374.38,3985.87 374.38,3785.87 474.38,3785.87 474.38,3985.87
  pour cut-out: 604.38,4085.87 604.38,3785.87 704.38,3785.87 704.38,4085.87
  pour cut-out: 904.38,4085.87 904.38,3785.87 974.38,3785.87 1004.38,3815.87 1004.38,4085.87
  pour cut-out: 1159.38,4085.87 1159.38,3785.87 1259.38,3785.87 1259.38,4085.87
  pour cut-out: 959.38,3725.87 959.38,3625.87 1259.38,3625.87 1259.38,3725.87
  pour cut-out: 1109.38,4735.87 1109.38,4635.87 1409.38,4635.87 1409.38,4735.87
  pour cut-out: 1109.38,4815.87 1409.38,4815.87 1409.38,4915.87 1109.38,4915.87
  pour cut-out: 1014.38,5120.87 1014.38,5025.87 1204.38,5025.87 1204.38,5120.87
  pour cut-out: 1054.38,2735.87 1154.38,2735.87 1154.38,2921.37 1134.88,2940.87 1054.38,2940.87
  pour cut-out: 1029.38,2750.87 1029.38,2850.87 829.38,2850.87 829.38,2750.87
  pour cut-out: 889.38,3160.87 889.38,2860.87 789.38,2860.87 789.38,3160.87
  pour cut-out: 789.38,3560.87 789.38,3360.87 889.38,3360.87 889.38,3560.87
  pour cut-out: 2311.5,4963 2311.5,4743 2411.5,4743 2411.5,4963
  text ".Layer_Name" at -2051,-674.49 h60
Layer 5 - PWR:
  text ".Layer_Name" at -2051,-674.49 h60
Layer 6 - Bottom Layer:
  region net GND: 482,294 1292,294 1292,324 482,324
  region net EXT_3V3: 1102,457.87 1102,479 1026.2,479 1005.07,457.87 1005.07,396.87 1102,396.87
  region net EXT_1V8: 1125.07,396.87 1170.07,396.87 1190.07,416.87 1190.07,441.87 1174.07,457.87 1125.07,457.87
  region net GND: 674.38,1840.87 724.38,1840.87 937.38,1627.87 937.38,1553.87 929.38,1545.87 884.38,1545.87 809.38,1470.87 704.38,1470.87 559.38,1615.87 559.38,1695.87 664.38,1695.87 684.38,1715.87 684.38,1755.87 674.38,1765.87
  region net GND: 1054.38,1395.87 1086.38,1395.87 1124.38,1433.87 1124.38,1515.87 1084.38,1515.87 1054.38,1485.87
  region net GND: 524.38,4225.87 524.38,4135.87 574.38,4135.87 574.38,4225.87
  region net GND: 779.38,4220.87 769.38,4210.87 769.38,4160.87 779.38,4150.87 839.38,4150.87 839.38,4220.87
  region net VOUT_SEPIC: 1269.38,5275.87 1269.38,5125.87 1364.38,5125.87 1364.38,5260.87 1349.38,5275.87
  region net GND: 1459.38,5295.87 1409.38,5295.87 1400.38,5286.87 1400.38,5089.87 1409.38,5080.87 1459.38,5080.87
  region net GND: 1119.38,4125.87 1059.38,4125.87 1044.38,4140.87 1044.38,4220.87 1089.38,4220.87 1119.38,4190.87
  region net LOCAL_3V3: 984.38,4195.87 924.38,4195.87 909.38,4180.87 909.38,4140.87 924.38,4125.87 984.38,4125.87
  region net LOCAL_1V8: 703.38,4220.87 658.38,4220.87 628.38,4190.87 628.38,4130.87 683.38,4130.87 703.38,4150.87
  region net LOCAL_1V1: 439.38,4155.87 389.38,4155.87 374.38,4170.87 374.38,4210.87 389.38,4225.87 439.38,4225.87
  region net VBAT: 739.38,6030.87 669.38,6030.87 609.38,5970.87 609.38,5800.87 739.38,5800.87
  region net NetD1_2: 784.38,5800.87 1034.38,5800.87 1034.38,5920.87 784.38,5920.87
  region net GND: 1034.38,6100.87 809.38,6100.87 809.38,5950.87 1034.38,5950.87
  region net GND: 20,6115 20,40 40,40 40,6095 2426,6095 2426,40 20,40 20,20 2447,20 2447,6115
  region net GND: 2320,5001 2320,4963 2403,4963 2403,5001
  text ".Layer_Name" at -2051,-674.49 h60

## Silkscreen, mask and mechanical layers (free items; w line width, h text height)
Top Overlay:
  lines w7: 254.38,3545.87 254.38,4090.87 254.38,4535.87 ; 49.38,4090.87 49.38,4535.87 314.38,4535.87 314.38,4090.87 ; 49.38,4090.87 314.38,4090.87 ; 49.38,4090.87 49.38,3545.87 314.38,3545.87 314.38,4090.87
  text "VIN" at 564.38,6085.87 h72.83 r270
  text "GND" at 939.38,6085.87 h72.83 r270
  text "VOUT" at 1422.38,5086.87 h50 r270
  text "PG" at 2242.38,4960.87 h50
  text "3V3" at 2242.38,4915.87 h50
  text "V MAIN" at 1064.38,4860.87 h50 r270
  text "EXT VIN" at 1419.38,4860.87 h50 r270
  text "PG" at 2242.38,4860.87 h50
  text "1V8" at 2242.38,4815.87 h50
  text "PG" at 2242.38,4760.87 h50
  text "1V1" at 2242.38,4715.87 h50
  text "MAIN" at 169.38,4520.87 h50 r270
  text "3V3" at 169.38,4395.87 h50 r270
  text "POWER" at 269.38,4380.87 h50 r270
  text "1V8" at 169.38,4285.87 h50 r270
  text "1V1" at 169.38,4175.87 h50 r270
  text "LOCAL" at 554.01,4145.87 h50 r270
  text "LOCAL" at 859.38,4145.87 h50 r270
  text "LOCAL" at 329.38,4010.87 h50 r270
  text "1V8" at 554.01,3975.87 h50 r270
  text "3V3" at 859.38,3975.87 h50 r270
  text "Camera 4" at 1832,3924 h72.83 r270
  text "MSP430" at 269.38,3890.87 h50 r270
  text "EXT" at 554.01,3875.87 h50 r270
  text "EXT" at 859.38,3875.87 h50 r270
  text "1V1" at 329.38,3840.87 h50 r270
  text "VCAM 1" at 554.38,3775.87 h50 r270
  text "VCAM 2" at 329.38,3755.87 h50 r270
  text "7" at 353.88,3348.45 h50 r270
  text "7" at 743.88,3348.45 h50 r270
  text "6" at 353.88,3248.45 h50 r270
  text "6" at 743.88,3248.45 h50 r270
  text "5" at 353.88,3148.45 h50 r270
  text "5" at 743.88,3148.45 h50 r270
  text "Camera 3" at 1832,3124 h72.83 r270
  text "4" at 353.88,3048.45 h50 r270
  text "4" at 743.88,3048.45 h50 r270
  text "3" at 353.88,2948.45 h50 r270
  text "3" at 743.88,2948.45 h50 r270
  text "2" at 353.88,2848.45 h50 r270
  text "2" at 743.88,2848.45 h50 r270
  text "1" at 353.88,2748.45 h50 r270
  text "1" at 743.88,2748.45 h50 r270
  text "VCAM 3" at 1049.38,2725.87 h50 r270
  text "0" at 353.88,2648.45 h50 r270
  text "0" at 743.88,2648.45 h50 r270
  text "VCAM 4" at 1049.38,2545.87 h50 r270
  text "GPIO" at 509.38,2530.87 h50
  text "USR" at 1122.38,2311.39 h72.83 r270
  text "Camera 2" at 1832,2274 h72.83 r270
  text "TDIO" at 1122.38,2105.16 h72.83 r270
  text "Camera 1" at 1832,1429 h72.83 r270
  text "TIDA-01323 E1" at 1592,1034 h90 r270
  text ".Layer_Name" at -2051,-674.49 h60
Bottom Overlay:
  text ".Layer_Name" at -2051,-674.49 h60
Top Paste:
  text ".Layer_Name" at -2051,-674.49 h60
Bottom Paste:
  text ".Layer_Name" at -2051,-674.49 h60
Top Solder:
  region: 20,6115 20,40 40,40 40,6095 2426,6095 2426,40 20,40 20,20 2447,20 2447,6115
  text ".Layer_Name" at -2051,-674.49 h60
  text ".Layer_Name" at -2051,-674.49 h60
Bottom Solder:
  region: 20,6115 20,40 40,40 40,6095 2426,6095 2426,40 20,40 20,20 2447,20 2447,6115
  text ".Layer_Name" at -2051,-674.49 h60
Drill Guide:
  text ".Layer_Name" at -2051,-674.49 h60
M1 Board Outline:
  lines w10: 0,0 2467,0 2467,6135 0,6135 0,0
  text ".Layer_Name" at -2051,-674.49 h60
M2 Board Dimensions:
  rectangle: -2629.87,-13.62 -2504.87,111.38
  rectangle: -2504.87,-138.62 -2129.87,-13.62
  lines w7: -2629.87,-13.62 -1629.87,-13.62 ; -2504.87,-138.62 -2504.87,111.38 ; -2379.87,-138.62 -2379.87,111.38 ; -2129.87,-138.62 -2129.87,111.38 ; -1879.87,-138.62 -1879.87,111.38 ; -2629.87,-138.62 -1629.87,-138.62 -1629.87,111.38 -2629.87,111.38 -2629.87,-138.62
  text ".Layer_Name" at -2051,-674.49 h60
M3 3D STEP Top:
  text ".Layer_Name" at -2051,-674.49 h60
M4 3D STEP Bottom:
  text ".Layer_Name" at -2051,-674.49 h60
M5 Assembly Top:
  lines w10: -2920,-746.17 3680,-746.17 ; -2920,-542.83 3682,-542.83 ; -2920,-339.5 -2920,-949.5 1085,-949.5 3682,-949.5 3682,-339.5 -2919.5,-339.5 -2919.5,-949.5 -1344,-949.5 ; -455,-949.5 -455,-339.5 ; 812,-542.83 812,-339.5 ; 1652,-542.83 1652,-339.5 ; 2274,-956 2274,-753.17
  text "COMPONENTS MARKED 'DNP' SHOULD NOT BE POPULATED." at -48,-71 h60
  text "ASSEMBLY VARIANT:" at -43,-191 h60
  text ".VariantName" at 957,-191 h60
  text "BOARD #:" at -393,-471 h60
  text "PCB VIEWED FROM TOP SIDE" at -2856.5,-471.67 h60
  text ".PRJ_Number" at 165.5,-471.67 h60
  text "REV:" at 1010,-471.67 h60
  text ".PCB_Rev" at 1301.5,-471.67 h60
  text "SVN REV:" at 1848,-471.67 h60
  text ".VersionControl_RevNumber" at 2354,-471.67 h60
  text "TID #:" at -380,-675 h60
  text ".TID" at 165.5,-675 h60
  text "PLOT NAME =" at -2856.5,-880.34 h60
  text ".plot_File_Name" at -2051,-880.34 h60
  text "GENERATED    :" at -378,-880.34 h60
  text ".Print_Date" at 491.5,-880.34 h60
  text ".Print_Time" at 1220.5,-880.34 h60
  text "TEXAS INSTRUMENTS" at 2485,-880.34 h60
M6 Assembly Bottom:
  lines w10: -2920.5,-543.33 3681.5,-543.33 ; -2918.5,-746.67 3681.5,-746.67 ; -1512.5,-956.5 -1512.5,-753.67 ; -890.5,-543.33 -890.5,-340 ; -50.5,-543.33 -50.5,-340 ; 1216.5,-950 1216.5,-340 ; 2105.5,-950 3681,-950 3681,-340 -2920.5,-340 -2920.5,-950 -323.5,-950 3681.5,-950 3681.5,-340
  text "COMPONENTS MARKED 'DNP' SHOULD NOT BE POPULATED." at 2746,-69 h60
  text ".VariantName" at 1777,-191 h60
  text "ASSEMBLY VARIANT:" at 2756,-191 h60
  text ".VersionControl_RevNumber" at -1592.5,-472.17 h60
  text "SVN REV:" at -1086.5,-472.17 h60
  text ".PCB_Rev" at -540,-472.17 h60
  text "REV:" at -248.5,-472.17 h60
  text ".PRJ_Number" at 596,-472.17 h60
  text "BOARD #:" at 1141.5,-472.17 h60
  text "PCB VIEWED FROM BOTTOM SIDE" at 3618,-472.17 h60
  text ".TID" at 596,-675.5 h60
  text "TID #:" at 1141.5,-675.5 h60
  text "TEXAS INSTRUMENTS" at -1723.5,-880.84 h60
  text ".Print_Time" at -459,-880.84 h60
  text ".Print_Date" at 270,-880.84 h60
  text "GENERATED    :" at 1139.5,-880.84 h60
  text ".plot_File_Name" at 2812.5,-880.84 h60
  text "PLOT NAME =" at 3618,-880.84 h60
M9 Title Sheet:
  drawing of 1178 lines, arcs and shapes, not listed
  text "1" at -1888.16,8220.5 h70
  text "2" at 607.5,8220.5 h70
  text "3" at 3096.84,8220.5 h70
  text "4" at 5603.51,8220.5 h70
  text "5" at 8102.5,8220.5 h70
  text "6" at 10607.5,8220.5 h70
  text "A" at -3044.5,7077.5 h70
  text "A" at 11755.5,7077.5 h70
  text "B" at -3044.5,4697.5 h70
  text "B" at 11755.5,4697.5 h70
  text "C" at -3044.5,2322.5 h70
  text "C" at 11755.5,2322.5 h70
  text "PROJECT TITLE:" at 8715.5,461.5 h45
  text ".PRJ_Title" at 8765.5,328.17 h70
  text "DESIGNED FOR:" at 8715.5,160.5 h45
  text ".PRJ_Customer" at 8765.5,20.5 h70
  text "D" at -3044.5,-47.5 h70
  text "D" at 11755.5,-47.5 h70
  text "FILE NAME:" at 8715.5,-139.5 h45
  text ".PCB_File_Name_No_Path" at 8765.5,-259.5 h70
  text "Texas Instruments (TI) and/or its licensors do not warrant the accuracy or completeness of this specification" at 3746,-421.34 h45
  text "ENGINEER:" at 8715.5,-429.5 h45
  text "LAYOUT BY:" at 10220.5,-429.5 h45
  text "or any information contained therein. TI and/or its licensors do not warrant that this design will meet" at 3701.01,-534 h45
  text ".PRJ_Engineer" at 8765.5,-584.49 h70
  text "JMM" at 10224,-616 h100
  text "s  o  l  u  t  i  o  n  s" at 11082,-619 h68
  text "the specifications, will be suitable for your application or fit for any particular purpose, or will operate in" at 3701.01,-646.67 h45
  text ".Layer_Name" at -2051,-674.49 h60
  text "ALTIUM DESIGNER VERSION:" at 10220.5,-739.5 h45
  text "an implementation. TI and/or its licensors do not warrant that the design is production worthy. You should" at 3701.01,-759.33 h45
  text "completely validate and test your design implementation to confirm the system functionality for your application." at 3746,-872 h45
  text ".print_Scale" at 8765.5,-872.83 h70
  text ".Application_BuildNumber" at 10271,-872.83 h70
  text "1" at -1888.16,-1079.5 h70
  text "2" at 607.5,-1079.5 h70
  text "3" at 3096.84,-1079.5 h70
  text "4" at 5603.51,-1079.5 h70
  text "5" at 8102.5,-1079.5 h70
  text "6" at 10607.5,-1079.5 h70
M10 Fab Notes:
  drawing of 174 lines, arcs and shapes, not listed
  text "DESIGN INFORMATION" at 9750.02,6385 h60
  text "MIN. TRACK WIDTH:" at 9105.46,6205 h60
  text "5" at 10201.7,6205 h60
  text "MIL" at 10356.46,6205 h60
  text "MIN. CLEARANCE:" at 9105.46,6073 h60
  text "0.2" at 10141.7,6073 h60
  text "mm" at 10356.46,6073 h60
  text "Fabrication Notes:" at 3612,5959 h200
  text "MIN. VIA PAD SIZE:" at 9105.46,5941 h60
  text "12" at 10171.71,5941 h60
  text "MIL" at 10356.46,5941 h60
  text "0.05mm (2MIL)" at 9800.46,5799.29 h60
  text "MINIMUM ANNULAR RING" at 8776.23,5795 h60
  text "EXTERNAL" at 10508.46,5795 h60
  text "Via Tenting - All vias are to be fully tented on top and bottom solder layers." at 3612,5774 h150
  text "PER" at 8976.23,5677 h60
  text "IPC-D-275 CLASS 2 LEVEL C" at 9196.23,5677 h60
  text "Impedance Control - Top layer contains 50 ohm (+/- 10%) single ended" at 3612,5634 h150
  text "MIL, HOLES" at 10684.46,5564.71 h60
  text "+/-" at 10292,5564 h60
  text "+/-" at 11146,5564 h60
  text "REGISTRATION TOLERANCES:" at 8776.23,5559 h60
  text "METAL" at 9976,5559 h60
  text "5" at 10552.2,5559 h60
  text "3" at 11385.2,5559 h60
  text "MIL" at 11501.46,5559 h60
  text "impedance using 15 mil width traces." at 3612,5494 h150
  text "+/-" at 11146,5446 h60
  text "HOLE SIZE TOLERANCE (UNLESS OTHERWISE SPECIFIED):" at 8776.23,5441 h60
  text "3" at 11385.2,5441 h60
  text "MIL" at 11501.46,5441 h60
  text "Impedance Control - Layer 3 contains 100 ohm (+/- 10%) differential pair" at 3612,5354 h150
  text "MATERIAL:" at 8701.46,5231.54 h60
  text "impedance using 5 mil width traces with 5 mil spacing." at 3612,5214 h150
  text "FR-4 High Tg" at 9687.9,5091.21 h60
  text "FR-408" at 9122.46,5082.64 h60
  text "OTHER" at 10610.46,5082.64 h60
  text "X" at 9533,5079 h60
  text "62 MIL (1.6mm) +/-10%" at 9442.56,4919.92 h60
  text "THICKNESS:" at 8776.23,4915.64 h60
  text "X" at 9314.4,4915.64 h60
  text "OTHER" at 10727.46,4915.64 h60
  text "TOLERANCE:" at 8776.23,4757.64 h60
  text "X" at 9615.53,4757.64 h60
  text "ANSI IPC-6012 TYPE 3 CLASS 2" at 9802.48,4757.64 h60
  text "OTHER +/-" at 9802.46,4601.64 h60
  text "BOW & TWIST:" at 8776.23,4444.64 h60
  text "X" at 9615.53,4444.64 h60
  text "ANSI IPC-6012 TYPE 3 CLASS 2" at 9802.48,4444.64 h60
  text "OTHER +/-" at 9802.46,4286.13 h60
  text "DRILLING:" at 8701.46,4147.64 h60
  text "REFERENCE:" at 8776.23,4030.64 h60
  text "X" at 9424.46,4030.64 h60
  text "AS SHOWN" at 9611.46,4030.64 h60
  text "X" at 10325.46,4030.64 h60
  text "NC_DRILL FILES" at 10462.46,4030.64 h60
  text "PTH COPPER THICKNESS:" at 8776.23,3872.64 h60
  text "X" at 9906.46,3872.64 h60
  text "20-30 um" at 10043.46,3872.64 h60
  text "OTHER" at 10760.46,3872.64 h60
  text "BOARD FINISH:" at 8701.46,3713.64 h60
  text "SILKSCREEN:" at 8856.68,3595.64 h60
  text "X" at 9805.46,3595.64 h60
  text "TOP" at 9931.46,3595.64 h60
  text "X" at 10315.46,3595.64 h60
  text "BOTTOM" at 10442.46,3595.64 h60
  text "SILKSCREEN COLOR:" at 8856.68,3428.64 h60
  text "X" at 9804.42,3428.64 h60
  text "WHITE" at 9931.46,3428.64 h60
  text "OTHER" at 10442.46,3428.64 h60
  text "GREEN" at 10062.46,3269.44 h60
  text "X" at 10527.42,3269.44 h60
  text "OTHER" at 10680.46,3269.44 h60
  text "BLACK" at 11167,3269 h60
  text "SOLDER RESIST COLOR:" at 8856.68,3258.64 h60
  text "X" at 9935.42,3099.44 h60
  text "MATTE" at 10062.46,3099.44 h60
  text "SEMI-GLOSS" at 10680,3098.8 h60
  text "IMMERSION GOLD (ENIG)" at 9762.46,2910.92 h60
  text "ENEPIG" at 11100,2907.64 h60
  text "SURFACE FINISH:" at 8701.46,2906.64 h60
  text "X" at 9575.51,2906.64 h60
  text "IMM. TIN/SILVER OR EQUIV" at 9031,2749.64 h60
  text "OTHER" at 10462.46,2749.64 h60
  text "ARRAY/PANEL:" at 8701.46,2570.64 h60
  text "CUT AND TRIM PER M1 BOARD OUTLINE" at 9762.46,2566.35 h60
  text "N.C. ROUTE" at 9762.46,2414.64 h60
  text "X" at 10441.46,2414.64 h60
  text "V. SCORE" at 10628.46,2414.64 h60
  text "CERTIFICATION:" at 8701.46,2277.64 h60
  text "MATERIALS AND WORKMANSHIP FOR ALL PCBS" at 9426.46,2277.64 h60
  text "TO MEET OR EXCEED THE REQUIREMENTS OF:" at 9426.46,2179.64 h60
  text "X" at 9052.96,2043.13 h60
  text "ANSI IPC-A-600F CLASS ->" at 9191.96,2043.13 h60
  text "X" at 10831.02,2043.13 h60
  text "2" at 10949.96,2043.14 h60
  text "1" at 10634.96,2041.64 h60
  text "3" at 11303.96,2041.64 h60
  text "X" at 9867.02,1883.64 h60
  text "RoHS" at 10003.96,1883.64 h60
  text "OTHER" at 10648.36,1883.64 h60
  text "PER ORDER" at 11045.42,1883.64 h60
  text "ALL BOARDS MUST MEET OR EXCEED UL94-V0 REQUIREMENTS." at 8729,1718 h60
  text "PCB MUST BEAR THE UL94V-0 UL REGISTERED MATERIAL ID NUMBER" at 8729,1598 h60
  text "ADDITIONAL REQUIREMENTS:" at 8701.46,1424.64 h60
  text "MICROSECTION:" at 8776.23,1309.64 h60
  text "YES" at 9681.96,1309.64 h60
  text "REQUIRED" at 10543.46,1153.49 h60
  text "BARE BOARD ELEC. TEST:" at 8776.23,1150.64 h60
  text "NONE" at 10081.96,1150.64 h60
  text "X" at 10416.46,1150.64 h60
  text "PER ORDER" at 11135.46,1150.64 h60
  text ".Layer_Name" at -2051,-674.49 h60
M11 Gerber Information:
  lines w10: -2920,-746.17 3680,-746.17 ; -2920,-542.83 3682,-542.83 ; -2920,-339.5 -2920,-949.5 1085,-949.5 3682,-949.5 3682,-339.5 -2919.5,-339.5 -2919.5,-949.5 -1344,-949.5 ; -455,-949.5 -455,-339.5 ; 812,-542.83 812,-339.5 ; 1652,-542.83 1652,-339.5 ; 2274,-956 2274,-753.17
  text "ALL ARTWORK VIEWED FROM TOP SIDE" at -2856.5,-471.67 h60
  text "BOARD #:" at -380,-471.67 h60
  text ".PRJ_Number" at 165.5,-471.67 h60
  text "REV:" at 1010,-471.67 h60
  text ".PCB_Rev" at 1301.5,-471.67 h60
  text "SVN REV:" at 1848,-471.67 h60
  text ".VersionControl_RevNumber" at 2354,-471.67 h60
  text "LAYER NAME =" at -2856.5,-674.49 h60
  text "TID #:" at -380,-675 h60
  text ".TID" at 165.5,-675 h60
  text "PLOT NAME =" at -2856.5,-880.34 h60
  text ".plot_File_Name" at -2051,-880.34 h60
  text "GENERATED    :" at -378,-880.34 h60
  text ".Print_Date" at 491.5,-880.34 h60
  text ".Print_Time" at 1220.5,-880.34 h60
  text "TEXAS INSTRUMENTS" at 2485,-880.34 h60
M12 Stackup:
  drawing of 399 lines, arcs and shapes, not listed
  text "Layer" at 3659.5,8001.5 h60
  text "Name" at 4069.41,8001.5 h60
  text "Material" at 5479,8001.5 h60
  text "Thickness" at 6338.77,8001.5 h60
  text "Constant" at 6988.6,8001.5 h60
  text "Board Layer Stack" at 7558.47,8001.5 h60
  text "1" at 3659.5,7881.5 h60
  text "Top Overlay" at 4069.41,7881.5 h60
  text "2" at 3659.5,7761.5 h60
  text "Top Solder" at 4069.41,7761.5 h60
  text "Solder Resist" at 5479,7761.5 h60
  text "0.40mil" at 6338.77,7761.5 h60
  text "3.5" at 6988.6,7761.5 h60
  text "3" at 3659.5,7641.5 h60
  text "Layer 1 - Top Layer" at 4069.41,7641.5 h60
  text "Copper" at 5479,7641.5 h60
  text "1.40mil" at 6338.77,7641.5 h60
  text "4" at 3659.5,7521.5 h60
  text "Dielectric 1" at 4069.41,7521.5 h60
  text "370HR" at 5479,7521.5 h60
  text "10.00mil" at 6338.77,7521.5 h60
  text "4.2" at 6988.6,7521.5 h60
  text "5" at 3659.5,7401.5 h60
  text "Layer 2 - GND" at 4069.41,7401.5 h60
  text "Copper" at 5479,7401.5 h60
  text "1.42mil" at 6338.77,7401.5 h60
  text "6" at 3659.5,7281.5 h60
  text "Dielectric 2" at 4069.41,7281.5 h60
  text "370HR" at 5479,7281.5 h60
  text "7.00mil" at 6338.77,7281.5 h60
  text "4.2" at 6988.6,7281.5 h60
  text "7" at 3659.5,7161.5 h60
  text "Layer 3 - Sensitive" at 4069.41,7161.5 h60
  text "Copper" at 5479,7161.5 h60
  text "1.42mil" at 6338.77,7161.5 h60
  text "8" at 3659.5,7041.5 h60
  text "Dielectric 3" at 4069.41,7041.5 h60
  text "370HR" at 5479,7041.5 h60
  text "20.00mil" at 6338.77,7041.5 h60
  text "4.2" at 6988.6,7041.5 h60
  text "9" at 3659.5,6921.5 h60
  text "Layer 4 - GND" at 4069.41,6921.5 h60
  text "Copper" at 5479,6921.5 h60
  text "1.42mil" at 6338.77,6921.5 h60
  text "10" at 3659.5,6801.5 h60
  text "Dielectric 4" at 4069.41,6801.5 h60
  text "370HR" at 5479,6801.5 h60
  text "7.00mil" at 6338.77,6801.5 h60
  text "4.2" at 6988.6,6801.5 h60
  text "11" at 3659.5,6681.5 h60
  text "Layer 5 - PWR" at 4069.41,6681.5 h60
  text "Copper" at 5479,6681.5 h60
  text "1.42mil" at 6338.77,6681.5 h60
  text "12" at 3659.5,6561.5 h60
  text "Dielectric 5" at 4069.41,6561.5 h60
  text "370HR" at 5479,6561.5 h60
  text "10.00mil" at 6338.77,6561.5 h60
  text "4.2" at 6988.6,6561.5 h60
  text "13" at 3659.5,6441.5 h60
  text "Layer 6 - Bottom Layer" at 4069.41,6441.5 h60
  text "Copper" at 5479,6441.5 h60
  text "1.40mil" at 6338.77,6441.5 h60
  text "14" at 3659.5,6321.5 h60
  text "Bottom Solder" at 4069.41,6321.5 h60
  text "Solder Resist" at 5479,6321.5 h60
  text "0.40mil" at 6338.77,6321.5 h60
  text "3.5" at 6988.6,6321.5 h60
  text "15" at 3659.5,6201.5 h60
  text "Bottom Overlay" at 4069.41,6201.5 h60
  text ".Layer_Name" at -2051,-674.49 h60
M13 Component Bodies Top:
  text ".Layer_Name" at -2051,-674.49 h60
M14 Component Bodies Bottom:
  text ".Layer_Name" at -2051,-674.49 h60
M15 Courtyards Top:
  text ".Layer_Name" at -2051,-674.49 h60
M16 Courtyards Bottom:
  text ".Layer_Name" at -2051,-674.49 h60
